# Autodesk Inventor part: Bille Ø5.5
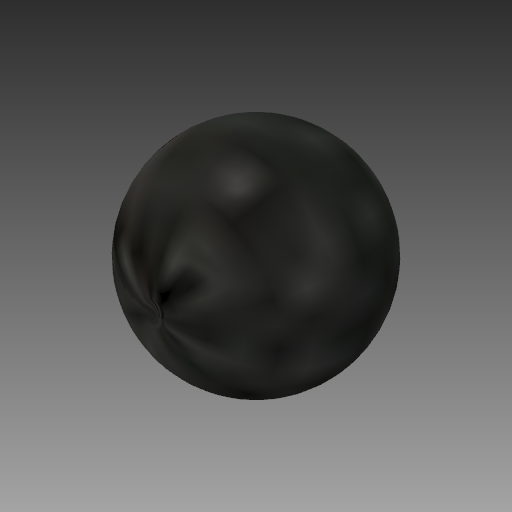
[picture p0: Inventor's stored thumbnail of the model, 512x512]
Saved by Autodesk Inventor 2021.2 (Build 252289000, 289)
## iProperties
Created: 2018-06
Part Number: Bille Ø5.5
Material: Acier
Document SubType Name: Modeling
Designer: Fabian Perrée
Density: 7.85 g/cm^3
Appearance: Plaque
Author: Fabian Perrée
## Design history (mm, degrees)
sketch "Esquisse1"
  geometry: L1 (0, 2.75)-(0, -2.75); A1 r 2.75 centre (0, 0) between (0, -2.75) and (0, 2.75); 2 further points
  constraints: 2 coincident, 2 end point, 2 point on circle, 1 centre point, 1 midpoint, 1 vertical
  dimensions: "d2" = 2.75 radius of A1
revolve "Révolution1" sketch "Esquisse1" stored, may be unused: angle "d3" = 90 deg
node "Solide1"
